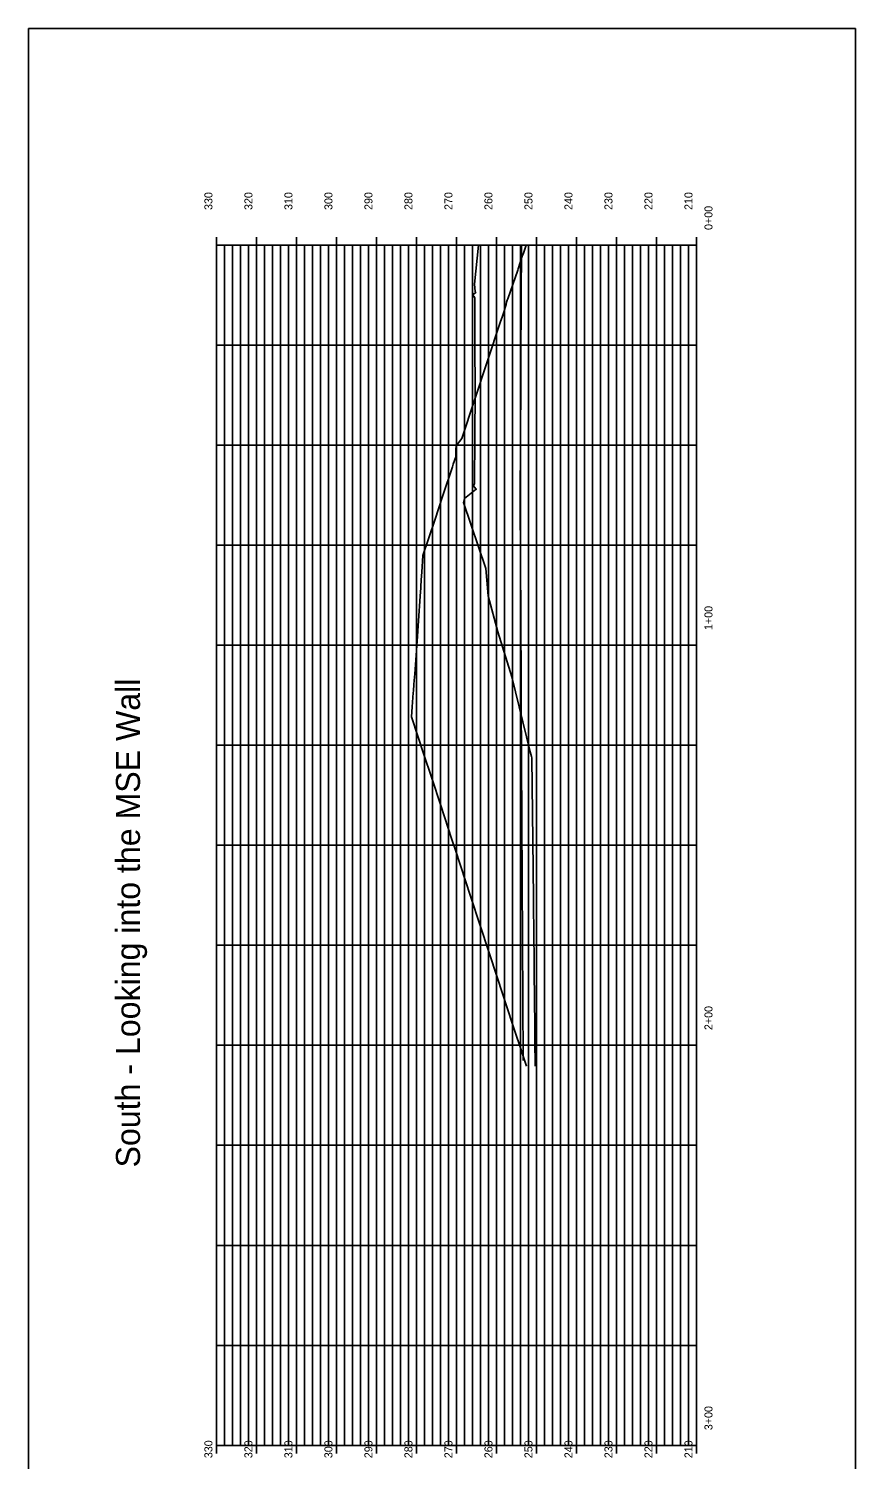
# Model space of a CAD drawing. Extents: x 1313293 to 1314187, y 2087928 to 2089557.
# Drawn here: x 1313949.1 to 1314155.7, y 2088639.2 to 2088996.8 of the extents above; entities that cross this region are included whole.
import ezdxf

# ---------------------------------------------------------------- set-up
doc = ezdxf.new("R2010")
doc.units = 0
for name, color, linetype in [('63', 7, 'Continuous'), ('B-Gen-Dimension', 7, 'Continuous'), ('B-Gen-Viewport', 7, 'Continuous'), ('R_Axis_Annotation', 7, 'Continuous'), ('R_Exist Surface', 7, 'Continuous'), ('R_Grid', 7, 'Continuous'), ('R_Grid Annot', 7, 'Continuous'), ('R_Grid_Minor', 7, 'Continuous'), ('R_Prop Surface', 7, 'Continuous')]:
    doc.layers.add(name, color=color, linetype=linetype)

msp = doc.modelspace()

# ---------------------------------------------------------------- linework, layer by layer
at = {"layer": 'B-Gen-Viewport'}
msp.add_lwpolyline([(1313949.07, 2088586.52), (1313949.07, 2088996.84), (1314155.74, 2088996.84), (1314155.74, 2088586.52)], close=True, dxfattribs=at)
at = {"layer": 'R_Exist Surface'}
msp.add_lwpolyline([(1314061.5, 2088942.71), (1314060.55, 2088932.93), (1314060.73, 2088931.14), (1314060.82, 2088930.82), (1314060.48, 2088930.64), (1314060.21, 2088930.12), (1314060.47, 2088929.84), (1314060.62, 2088929.43), (1314060.57, 2088918.28), (1314060.73, 2088906.18), (1314060.57, 2088894.78), (1314060.52, 2088883.13), (1314060.32, 2088882.67), (1314060.13, 2088882.46), (1314060.46, 2088882.31), (1314060.97, 2088881.71), (1314058.06, 2088879.41), (1314057.76, 2088878.41), (1314063.34, 2088861.89), (1314063.93, 2088855.02), (1314066.32, 2088846.08), (1314069.88, 2088834.77), (1314074.4, 2088816.04), (1314074.75, 2088814.94), (1314074.83, 2088814.56), (1314074.86, 2088814.45), (1314074.85, 2088814.36), (1314075.08, 2088793.96), (1314075.08, 2088793.96), (1314075.08, 2088793.96), (1314075.29, 2088779.48), (1314075.27, 2088777.73), (1314075.44, 2088763.71), (1314075.45, 2088761.04), (1314075.6, 2088747.47), (1314075.61, 2088744.07), (1314075.68, 2088737.51)], dxfattribs=at)
at = {"layer": 'R_Grid'}
for p, q in [((1314116.01, 2088942.71), (1313996.01, 2088942.71)), ((1313996.01, 2088942.71), (1313996.01, 2088642.71)), ((1313996.01, 2088942.71), (1313996.01, 2088642.71)), ((1314006.01, 2088942.71), (1314006.01, 2088642.71)), ((1314016.01, 2088942.71), (1314016.01, 2088642.71)), ((1314026.01, 2088942.71), (1314026.01, 2088642.71)), ((1314036.01, 2088942.71), (1314036.01, 2088642.71)), ((1314046.01, 2088942.71), (1314046.01, 2088642.71)), ((1314056.01, 2088942.71), (1314056.01, 2088642.71)), ((1314066.01, 2088942.71), (1314066.01, 2088642.71)), ((1314076.01, 2088942.71), (1314076.01, 2088642.71)), ((1314086.01, 2088942.71), (1314086.01, 2088642.71)), ((1314096.01, 2088942.71), (1314096.01, 2088642.71)), ((1314106.01, 2088942.71), (1314106.01, 2088642.71)), ((1314116.01, 2088942.71), (1314116.01, 2088642.71)), ((1314116.01, 2088842.71), (1313996.01, 2088842.71)), ((1314116.01, 2088742.71), (1313996.01, 2088742.71)), ((1314116.01, 2088642.71), (1313996.01, 2088642.71))]:
    msp.add_line(p, q, dxfattribs=at)
at = {"layer": 'R_Grid Annot'}
for p, q in [((1313996.01, 2088944.71), (1313996.01, 2088942.71)), ((1313996.01, 2088944.71), (1313996.01, 2088942.71)), ((1313998.01, 2088942.71), (1313998.01, 2088939.71)), ((1314000.01, 2088942.71), (1314000.01, 2088939.71)), ((1314002.01, 2088942.71), (1314002.01, 2088939.71)), ((1314004.01, 2088942.71), (1314004.01, 2088939.71)), ((1314006.01, 2088944.71), (1314006.01, 2088942.71)), ((1314008.01, 2088942.71), (1314008.01, 2088939.71)), ((1314010.01, 2088942.71), (1314010.01, 2088939.71)), ((1314012.01, 2088942.71), (1314012.01, 2088939.71)), ((1314014.01, 2088942.71), (1314014.01, 2088939.71)), ((1314016.01, 2088944.71), (1314016.01, 2088942.71)), ((1314018.01, 2088942.71), (1314018.01, 2088939.71)), ((1314020.01, 2088942.71), (1314020.01, 2088939.71)), ((1314022.01, 2088942.71), (1314022.01, 2088939.71)), ((1314024.01, 2088942.71), (1314024.01, 2088939.71)), ((1314026.01, 2088944.71), (1314026.01, 2088942.71)), ((1314028.01, 2088942.71), (1314028.01, 2088939.71)), ((1314030.01, 2088942.71), (1314030.01, 2088939.71)), ((1314032.01, 2088942.71), (1314032.01, 2088939.71)), ((1314034.01, 2088942.71), (1314034.01, 2088939.71)), ((1314036.01, 2088944.71), (1314036.01, 2088942.71)), ((1314038.01, 2088942.71), (1314038.01, 2088939.71)), ((1314040.01, 2088942.71), (1314040.01, 2088939.71)), ((1314042.01, 2088942.71), (1314042.01, 2088939.71)), ((1314044.01, 2088942.71), (1314044.01, 2088939.71)), ((1314046.01, 2088944.71), (1314046.01, 2088942.71)), ((1314048.01, 2088942.71), (1314048.01, 2088939.71)), ((1314050.01, 2088942.71), (1314050.01, 2088939.71)), ((1314052.01, 2088942.71), (1314052.01, 2088939.71)), ((1314054.01, 2088942.71), (1314054.01, 2088939.71)), ((1314056.01, 2088944.71), (1314056.01, 2088942.71)), ((1314058.01, 2088942.71), (1314058.01, 2088939.71)), ((1314060.01, 2088942.71), (1314060.01, 2088939.71)), ((1314062.01, 2088942.71), (1314062.01, 2088939.71)), ((1314064.01, 2088942.71), (1314064.01, 2088939.71)), ((1314066.01, 2088944.71), (1314066.01, 2088942.71)), ((1314068.01, 2088942.71), (1314068.01, 2088939.71)), ((1314070.01, 2088942.71), (1314070.01, 2088939.71)), ((1314072.01, 2088942.71), (1314072.01, 2088939.71)), ((1314074.01, 2088942.71), (1314074.01, 2088939.71)), ((1314076.01, 2088944.71), (1314076.01, 2088942.71)), ((1314078.01, 2088942.71), (1314078.01, 2088939.71)), ((1314080.01, 2088942.71), (1314080.01, 2088939.71)), ((1314082.01, 2088942.71), (1314082.01, 2088939.71)), ((1314084.01, 2088942.71), (1314084.01, 2088939.71)), ((1314086.01, 2088944.71), (1314086.01, 2088942.71)), ((1314088.01, 2088942.71), (1314088.01, 2088939.71)), ((1314090.01, 2088942.71), (1314090.01, 2088939.71)), ((1314092.01, 2088942.71), (1314092.01, 2088939.71)), ((1314094.01, 2088942.71), (1314094.01, 2088939.71)), ((1314096.01, 2088944.71), (1314096.01, 2088942.71)), ((1314098.01, 2088942.71), (1314098.01, 2088939.71)), ((1314100.01, 2088942.71), (1314100.01, 2088939.71)), ((1314102.01, 2088942.71), (1314102.01, 2088939.71)), ((1314104.01, 2088942.71), (1314104.01, 2088939.71)), ((1314106.01, 2088944.71), (1314106.01, 2088942.71)), ((1314108.01, 2088942.71), (1314108.01, 2088939.71)), ((1314110.01, 2088942.71), (1314110.01, 2088939.71)), ((1314112.01, 2088942.71), (1314112.01, 2088939.71)), ((1314114.01, 2088942.71), (1314114.01, 2088939.71)), ((1314116.01, 2088944.71), (1314116.01, 2088942.71)), ((1313996.01, 2088640.71), (1313996.01, 2088642.71)), ((1313996.01, 2088640.71), (1313996.01, 2088642.71)), ((1313998.01, 2088642.71), (1313998.01, 2088645.71)), ((1314000.01, 2088642.71), (1314000.01, 2088645.71)), ((1314002.01, 2088642.71), (1314002.01, 2088645.71)), ((1314004.01, 2088642.71), (1314004.01, 2088645.71)), ((1314006.01, 2088640.71), (1314006.01, 2088642.71)), ((1314008.01, 2088642.71), (1314008.01, 2088645.71)), ((1314010.01, 2088642.71), (1314010.01, 2088645.71)), ((1314012.01, 2088642.71), (1314012.01, 2088645.71)), ((1314014.01, 2088642.71), (1314014.01, 2088645.71)), ((1314016.01, 2088640.71), (1314016.01, 2088642.71)), ((1314018.01, 2088642.71), (1314018.01, 2088645.71)), ((1314020.01, 2088642.71), (1314020.01, 2088645.71)), ((1314022.01, 2088642.71), (1314022.01, 2088645.71)), ((1314024.01, 2088642.71), (1314024.01, 2088645.71)), ((1314026.01, 2088640.71), (1314026.01, 2088642.71)), ((1314028.01, 2088642.71), (1314028.01, 2088645.71)), ((1314030.01, 2088642.71), (1314030.01, 2088645.71)), ((1314032.01, 2088642.71), (1314032.01, 2088645.71)), ((1314034.01, 2088642.71), (1314034.01, 2088645.71)), ((1314036.01, 2088640.71), (1314036.01, 2088642.71)), ((1314038.01, 2088642.71), (1314038.01, 2088645.71)), ((1314040.01, 2088642.71), (1314040.01, 2088645.71)), ((1314042.01, 2088642.71), (1314042.01, 2088645.71)), ((1314044.01, 2088642.71), (1314044.01, 2088645.71)), ((1314046.01, 2088640.71), (1314046.01, 2088642.71)), ((1314048.01, 2088642.71), (1314048.01, 2088645.71)), ((1314050.01, 2088642.71), (1314050.01, 2088645.71)), ((1314052.01, 2088642.71), (1314052.01, 2088645.71)), ((1314054.01, 2088642.71), (1314054.01, 2088645.71)), ((1314056.01, 2088640.71), (1314056.01, 2088642.71)), ((1314058.01, 2088642.71), (1314058.01, 2088645.71)), ((1314060.01, 2088642.71), (1314060.01, 2088645.71)), ((1314062.01, 2088642.71), (1314062.01, 2088645.71)), ((1314064.01, 2088642.71), (1314064.01, 2088645.71)), ((1314066.01, 2088640.71), (1314066.01, 2088642.71)), ((1314068.01, 2088642.71), (1314068.01, 2088645.71)), ((1314070.01, 2088642.71), (1314070.01, 2088645.71)), ((1314072.01, 2088642.71), (1314072.01, 2088645.71)), ((1314074.01, 2088642.71), (1314074.01, 2088645.71)), ((1314076.01, 2088640.71), (1314076.01, 2088642.71)), ((1314078.01, 2088642.71), (1314078.01, 2088645.71)), ((1314080.01, 2088642.71), (1314080.01, 2088645.71)), ((1314082.01, 2088642.71), (1314082.01, 2088645.71)), ((1314084.01, 2088642.71), (1314084.01, 2088645.71)), ((1314086.01, 2088640.71), (1314086.01, 2088642.71)), ((1314088.01, 2088642.71), (1314088.01, 2088645.71)), ((1314090.01, 2088642.71), (1314090.01, 2088645.71)), ((1314092.01, 2088642.71), (1314092.01, 2088645.71)), ((1314094.01, 2088642.71), (1314094.01, 2088645.71)), ((1314096.01, 2088640.71), (1314096.01, 2088642.71)), ((1314098.01, 2088642.71), (1314098.01, 2088645.71)), ((1314100.01, 2088642.71), (1314100.01, 2088645.71)), ((1314102.01, 2088642.71), (1314102.01, 2088645.71)), ((1314104.01, 2088642.71), (1314104.01, 2088645.71)), ((1314106.01, 2088640.71), (1314106.01, 2088642.71)), ((1314108.01, 2088642.71), (1314108.01, 2088645.71)), ((1314110.01, 2088642.71), (1314110.01, 2088645.71)), ((1314112.01, 2088642.71), (1314112.01, 2088645.71)), ((1314114.01, 2088642.71), (1314114.01, 2088645.71)), ((1314116.01, 2088640.71), (1314116.01, 2088642.71))]:
    msp.add_line(p, q, dxfattribs=at)
at = {"layer": 'R_Grid_Minor'}
for p, q in [((1313998.01, 2088942.71), (1313998.01, 2088642.71)), ((1314000.01, 2088942.71), (1314000.01, 2088642.71)), ((1314002.01, 2088942.71), (1314002.01, 2088642.71)), ((1314004.01, 2088942.71), (1314004.01, 2088642.71)), ((1314008.01, 2088942.71), (1314008.01, 2088642.71)), ((1314010.01, 2088942.71), (1314010.01, 2088642.71)), ((1314012.01, 2088942.71), (1314012.01, 2088642.71)), ((1314014.01, 2088942.71), (1314014.01, 2088642.71)), ((1314018.01, 2088942.71), (1314018.01, 2088642.71)), ((1314020.01, 2088942.71), (1314020.01, 2088642.71)), ((1314022.01, 2088942.71), (1314022.01, 2088642.71)), ((1314024.01, 2088942.71), (1314024.01, 2088642.71)), ((1314028.01, 2088942.71), (1314028.01, 2088642.71)), ((1314030.01, 2088942.71), (1314030.01, 2088642.71)), ((1314032.01, 2088942.71), (1314032.01, 2088642.71)), ((1314034.01, 2088942.71), (1314034.01, 2088642.71)), ((1314038.01, 2088942.71), (1314038.01, 2088642.71)), ((1314040.01, 2088942.71), (1314040.01, 2088642.71)), ((1314042.01, 2088942.71), (1314042.01, 2088642.71)), ((1314044.01, 2088942.71), (1314044.01, 2088642.71)), ((1314048.01, 2088942.71), (1314048.01, 2088642.71)), ((1314050.01, 2088942.71), (1314050.01, 2088642.71)), ((1314052.01, 2088942.71), (1314052.01, 2088642.71)), ((1314054.01, 2088942.71), (1314054.01, 2088642.71)), ((1314058.01, 2088942.71), (1314058.01, 2088642.71)), ((1314060.01, 2088942.71), (1314060.01, 2088642.71)), ((1314062.01, 2088942.71), (1314062.01, 2088642.71)), ((1314064.01, 2088942.71), (1314064.01, 2088642.71)), ((1314068.01, 2088942.71), (1314068.01, 2088642.71)), ((1314070.01, 2088942.71), (1314070.01, 2088642.71)), ((1314072.01, 2088942.71), (1314072.01, 2088642.71)), ((1314074.01, 2088942.71), (1314074.01, 2088642.71)), ((1314078.01, 2088942.71), (1314078.01, 2088642.71)), ((1314080.01, 2088942.71), (1314080.01, 2088642.71)), ((1314082.01, 2088942.71), (1314082.01, 2088642.71)), ((1314084.01, 2088942.71), (1314084.01, 2088642.71)), ((1314088.01, 2088942.71), (1314088.01, 2088642.71)), ((1314090.01, 2088942.71), (1314090.01, 2088642.71)), ((1314092.01, 2088942.71), (1314092.01, 2088642.71)), ((1314094.01, 2088942.71), (1314094.01, 2088642.71)), ((1314098.01, 2088942.71), (1314098.01, 2088642.71)), ((1314100.01, 2088942.71), (1314100.01, 2088642.71)), ((1314102.01, 2088942.71), (1314102.01, 2088642.71)), ((1314104.01, 2088942.71), (1314104.01, 2088642.71)), ((1314108.01, 2088942.71), (1314108.01, 2088642.71)), ((1314110.01, 2088942.71), (1314110.01, 2088642.71)), ((1314112.01, 2088942.71), (1314112.01, 2088642.71)), ((1314114.01, 2088942.71), (1314114.01, 2088642.71)), ((1314116.01, 2088917.71), (1313996.01, 2088917.71)), ((1314116.01, 2088892.71), (1313996.01, 2088892.71)), ((1314116.01, 2088867.71), (1313996.01, 2088867.71)), ((1314116.01, 2088817.71), (1313996.01, 2088817.71)), ((1314116.01, 2088792.71), (1313996.01, 2088792.71)), ((1314116.01, 2088767.71), (1313996.01, 2088767.71)), ((1314116.01, 2088717.71), (1313996.01, 2088717.71)), ((1314116.01, 2088692.71), (1313996.01, 2088692.71)), ((1314116.01, 2088667.71), (1313996.01, 2088667.71))]:
    msp.add_line(p, q, dxfattribs=at)
at = {"layer": 'R_Prop Surface'}
for points in [[(1314073.4, 2088942.71), (1314072.66, 2088940.48), (1314072.55, 2088940.14), (1314072.48, 2088939.94), (1314071.45, 2088936.82), (1314071.32, 2088936.44), (1314068.86, 2088929.33), (1314068.78, 2088929.09), (1314068.72, 2088928.92), (1314068.55, 2088928.43), (1314068.46, 2088927.84), (1314068.22, 2088927.11), (1314067.92, 2088926.18), (1314067.61, 2088925.25), (1314067.52, 2088924.98), (1314066.97, 2088923.34), (1314057.37, 2088894.42), (1314055.91, 2088892.56), (1314055.89, 2088891.69), (1314055.85, 2088889.84), (1314055.23, 2088887.95), (1314055.02, 2088887.32), (1314052.62, 2088880.1), (1314050.58, 2088873.95), (1314047.65, 2088865.13), (1314047.36, 2088860.99), (1314047.23, 2088859.07), (1314047.11, 2088857.31), (1314047.09, 2088857.06), (1314046.94, 2088854.94), (1314046.51, 2088848.82), (1314046.24, 2088844.96), (1314045.99, 2088841.36), (1314045.57, 2088835.52), (1314045.45, 2088833.87), (1314045.38, 2088832.86), (1314045.27, 2088831.28), (1314045.23, 2088830.84), (1314044.98, 2088827.31), (1314044.8, 2088824.79), (1314046.37, 2088820.01), (1314047.8, 2088815.66), (1314049.83, 2088809.48), (1314052.08, 2088802.61), (1314054.88, 2088794.14), (1314055.76, 2088791.47), (1314059.56, 2088779.97), (1314061.95, 2088772.67), (1314066.26, 2088759.52), (1314068.72, 2088752.06), (1314070.13, 2088747.78), (1314071.05, 2088745), (1314071.69, 2088743.05), (1314072.16, 2088741.61), (1314072.53, 2088740.5), (1314073.51, 2088737.51)], [(1314072.25, 2088942.71), (1314072.19, 2088928.98), (1314072.19, 2088928.98), (1314072.17, 2088923.98), (1314072.17, 2088923.98), (1314072.17, 2088923.97), (1314072.14, 2088918.98), (1314072.14, 2088918.97), (1314072.12, 2088913.98), (1314072.12, 2088913.96), (1314072.1, 2088908.98), (1314072.1, 2088908.96), (1314072.07, 2088903.98), (1314072.05, 2088899.01), (1314072.05, 2088898.98), (1314072.05, 2088898.95), (1314072.03, 2088893.98), (1314072, 2088889.02), (1314072, 2088888.98), (1314072, 2088888.94), (1314071.98, 2088883.98), (1314071.98, 2088883.93), (1314071.95, 2088878.98), (1314071.97, 2088874.03), (1314071.97, 2088873.98), (1314071.97, 2088873.92), (1314071.99, 2088868.98), (1314071.99, 2088868.92), (1314072.02, 2088863.98), (1314072.05, 2088859.04), (1314072.05, 2088858.98), (1314072.07, 2088854.05), (1314072.07, 2088853.98), (1314072.07, 2088853.91), (1314072.1, 2088848.98), (1314072.1, 2088848.9), (1314072.13, 2088843.98), (1314072.13, 2088843.9), (1314072.15, 2088838.98), (1314072.15, 2088838.89), (1314072.18, 2088833.98), (1314072.2, 2088829.07), (1314072.2, 2088828.98), (1314072.21, 2088828.88), (1314072.23, 2088823.98), (1314072.23, 2088823.88), (1314072.26, 2088818.98), (1314072.26, 2088818.87), (1314072.28, 2088813.98), (1314072.29, 2088813.87), (1314072.31, 2088808.98), (1314072.31, 2088808.87), (1314072.34, 2088803.98), (1314072.34, 2088803.86), (1314072.36, 2088798.98), (1314072.36, 2088798.86), (1314072.39, 2088793.98), (1314072.42, 2088789.11), (1314072.42, 2088788.98), (1314072.42, 2088788.85), (1314072.44, 2088783.98), (1314072.44, 2088783.84), (1314072.47, 2088778.98), (1314072.47, 2088778.84), (1314072.5, 2088773.98), (1314072.5, 2088773.83), (1314072.52, 2088768.98), (1314072.52, 2088768.83), (1314072.55, 2088763.98), (1314072.55, 2088763.82), (1314072.58, 2088758.98), (1314072.58, 2088758.82), (1314072.6, 2088753.98), (1314072.6, 2088753.82), (1314072.63, 2088748.98), (1314072.63, 2088748.81), (1314072.66, 2088743.98), (1314072.66, 2088743.81), (1314072.68, 2088738.98), (1314072.68, 2088738.88)]]:
    msp.add_lwpolyline(points, dxfattribs=at)

# ---------------------------------------------------------------- texts
at = {"layer": '63'}
msp.add_text('-', height=0.0001, rotation=90, dxfattribs=at).set_placement((1314116.01, 2088942.71))
at = {"layer": 'B-Gen-Dimension'}
msp.add_text('South - Looking into the MSE Wall', height=6, rotation=90, dxfattribs=at).set_placement((1313976.9, 2088712.18))
at = {"layer": 'R_Axis_Annotation'}
for s, p in [('330', (1313995.01, 2088951.51)), ('330', (1313995.01, 2088951.51)), ('320', (1314005.01, 2088951.51)), ('310', (1314015.01, 2088951.51)), ('300', (1314025.01, 2088951.51)), ('290', (1314035.01, 2088951.51)), ('280', (1314045.01, 2088951.51)), ('270', (1314055.01, 2088951.51)), ('260', (1314065.01, 2088951.51)), ('250', (1314075.01, 2088951.51)), ('240', (1314085.01, 2088951.51)), ('230', (1314095.01, 2088951.51)), ('220', (1314105.01, 2088951.51)), ('210', (1314115.01, 2088951.51)), ('0+00', (1314120.01, 2088946.51)), ('1+00', (1314120.01, 2088846.51)), ('2+00', (1314120.01, 2088746.51)), ('3+00', (1314120.01, 2088646.51)), ('330', (1313995.01, 2088639.51)), ('330', (1313995.01, 2088639.51)), ('320', (1314005.01, 2088639.51)), ('310', (1314015.01, 2088639.51)), ('300', (1314025.01, 2088639.51)), ('290', (1314035.01, 2088639.51)), ('280', (1314045.01, 2088639.51)), ('270', (1314055.01, 2088639.51)), ('260', (1314065.01, 2088639.51)), ('250', (1314075.01, 2088639.51)), ('240', (1314085.01, 2088639.51)), ('230', (1314095.01, 2088639.51)), ('220', (1314105.01, 2088639.51)), ('210', (1314115.01, 2088639.51))]:
    msp.add_text(s, height=2, rotation=90, dxfattribs=at).set_placement(p)

doc.saveas('drawing.dxf')
